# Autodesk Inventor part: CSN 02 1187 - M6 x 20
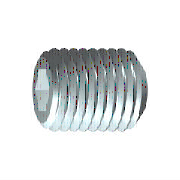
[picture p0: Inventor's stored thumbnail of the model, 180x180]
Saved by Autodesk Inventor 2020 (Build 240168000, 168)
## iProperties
Created: 2019-01
Part Number: CSN 02 1187 - M6 x 20
Material: Ocel, měkká
Description: Stavěcí šroub s vnitřním šestihranem s plochým kuželovým koncem
Document SubType Name: Modeling
Standard: CSN 02 1187
Designer: doma
Standards Organization: CSN
Language: cs-CZ
Size Designation: M6 x 20
Categories: <MemberInstance><Categories><Category DisplayName="Spojovací materiál" InternalName="e4da775c-781d-43d5-af7c-5136215cf5a6" Mnemonic="FSTN"><Category DisplayName
Density: 7.85 g/cm^3
Appearance: Pololeštěná
IsCustomPart: 0
Author: doma
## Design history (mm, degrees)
sketch "Náčrt1"
  geometry: L1 (0, 0)-(15, 0); L2 (20, 1.732)-(20, 3); L3 (20, 3)-(0, 3); L4 (20, 1.732)-(16, 1.732); L5 (16, 1.732)-(15, 0); L6 (0, -0.6)-(0, 3.6) reference; L7 (0, 3)-(0, 0)
  constraints: 13 end point, 3 parallel, 1 collinear, 1 perpendicular, 1 point on line
  dimensions: "d0" = 4 distance of L2.start L4.end (= INTI); "d1" = 60 deg angle of L5 L1; "d2" = 6 diameter of L3 L1 (= NND); "d3" = 3.4641 diameter of L4 L1 (= 1.1547 x SW); "d5" = 20 distance from line of L2 L3.end (= NLG)
revolve "Těleso" sketch "Náčrt1" stored, may be unused: angle "d6" = 90 deg
sketch "Náčrt2"
  geometry: L1 (-0.866, 1.5)-(0.866, 1.5); L2 (0.866, 1.5)-(1.732, 0); L3 (1.732, 0)-(0.866, -1.5); L4 (0.866, -1.5)-(-0.866, -1.5); L5 (-0.866, -1.5)-(-1.732, 0); L6 (-1.732, 0)-(-0.866, 1.5); A1 r 1.732 centre (0, 0) between (-0.866, 1.5) and (0.866, 1.5) reference; 2 further points
  constraints: 12 end point, 2 point on circle, 1 coincident, 1 horizontal, 11 other
extrude "Drážka" join sketch "Náčrt2" taper "d9" = 0 deg; stored distance "d21" = 10
workaxis "Work Axis1"
workplane "Work Plane1"
body "Solid1"
chamfer "Zkosení1" distance "d7" = 0.61345 (= -0.5 x GD1 + 0.5 x NND); stored, may be unused: angle "d8" = 60 deg (= FAWI), second distance "d29" = 0.61345 (= -0.5 x GD1 + 0.5 x NND)
feature "Závit" dims "d11" = 20 (= NLG), "d12" = 0
chamfer "Zkosení2" distance "d13" = 0.61345 (= -0.5 x GD1 + 0.5 x NND); stored, may be unused: angle "d14" = 60 deg (= FAWI), second distance "d30" = 0.61345 (= -0.5 x GD1 + 0.5 x NND)
other parameters: "NND" = 6 [user parameter; used in 6 equation terms], "NLG" = 20 [user parameter; used in 2 equation terms], "INTI" = 4 [user parameter; used in 1 equation term], "FAWI" = 60 deg [user parameter; used in 2 equation terms], "SW" = 3 [user parameter; used in 2 equation terms], "GD1" = 4.7731 (= THREADDIA - 1.2269 x PTC) [user parameter; used in 4 equation terms], "d4" = 0, "FAWI1" = 30 deg [user parameter], "d15" = 0, "d31" = 0, "GUL" = 0.61345 (= 0.61345 x PTC) [user parameter], "SPD" = 4.7731 (= NND - 1.2269 x PTC) [user parameter], "TOA" = 30 deg [user parameter], "THREADDIA" = 6 [user parameter; used in 1 equation term], "PTC" = 1 [user parameter; used in 5 equation terms], "GAL" = 0.61345 (= 0.61345 x PTC) [user parameter], "E0" = 3.465 (= 1.155 x SW) [user parameter]
